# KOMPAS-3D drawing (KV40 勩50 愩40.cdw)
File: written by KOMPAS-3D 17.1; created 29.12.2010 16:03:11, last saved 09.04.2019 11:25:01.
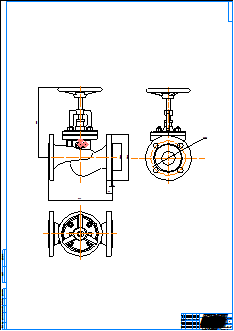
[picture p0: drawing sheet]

Title block, sheet 1: name: KV 40 Ду50; material: Внимание! Данный продукт является объектом авторского права ООО «Торговый Дом АДЛ». / Запрещается изменение, копирование, распространение / (в том числе путем копирования на другие сайты и ресурсы в Интернете) / или любое иное использование информации и объектов без предварительного / согласия правообладателя (ООО «Торговый Дом АДЛ»).; scale: 1:1; sheets: 1; organisation: ООО "Торговый дом АДЛ"; sheet format: A0; stored path: \\adlc.lan\data\АДЛ_ПКД\3D-модели\ADL production\Вентили ГРАНВЕНТ\KV40\KOMPAS 2D\KV 40 Ду50.cdw

Views: Вид 4, Спереди 1, Проекционный вид 3
Dimensions and other numbers on the sheet: 102; 165; 3; 20; 230; 125; 250; 1:1; 1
